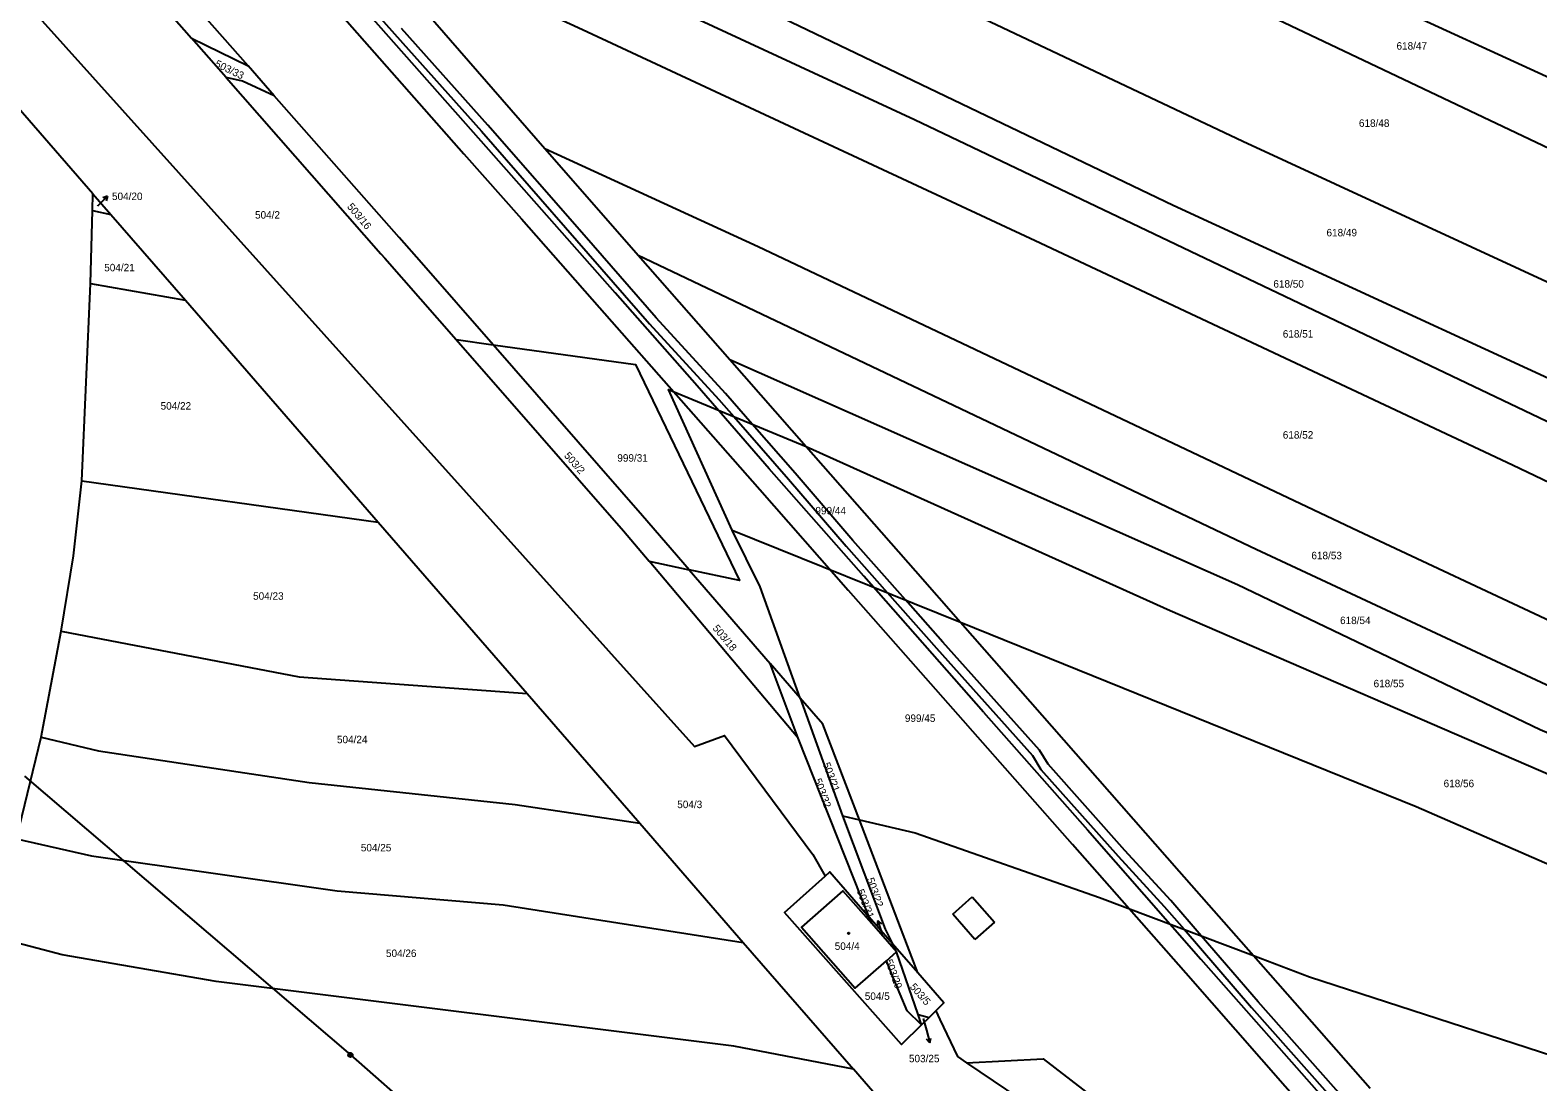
# Model space of a CAD drawing. Extents: x -757266 to -753360, y -1162585 to -1157740.
# Drawn here: x -755892 to -755548.3, y -1161804.6 to -1161564.9 of the extents above; entities that cross this region are included whole.
import ezdxf

# ---------------------------------------------------------------- set-up
doc = ezdxf.new("R2010")
doc.units = 0
for name, color, linetype in [('Hranice parcel', 7, 'Continuous'), ('Parcelní čísla', 7, 'Continuous'), ('Pop  PČ popisy', 7, 'Continuous'), ('Poz předměty', 7, 'Continuous'), ('Vnitřní kresba', 7, 'Continuous'), ('Věcná břemena k části', 7, 'Continuous'), ('Značky budov', 7, 'Continuous')]:
    doc.layers.add(name, color=color, linetype=linetype)

msp = doc.modelspace()

# ---------------------------------------------------------------- linework, layer by layer
at = {"layer": 'Hranice parcel'}
for p, q in [((-755847.28, -1161575.69), (-755855.21, -1161566.66)), ((-755855.21, -1161566.66), (-755842.32, -1161573.01)), ((-755877.68, -1161602.17), (-755901.54, -1161574.72)), ((-755836.33, -1161579.81), (-755842.32, -1161573.01)), ((-755877.79, -1161605.96), (-755877.68, -1161602.17)), ((-755877.68, -1161602.17), (-755873.56, -1161606.91)), ((-755878.21, -1161622.6), (-755877.79, -1161605.96)), ((-755877.79, -1161605.96), (-755873.56, -1161606.91)), ((-755873.56, -1161606.91), (-755856.6, -1161626.43)), ((-755753.39, -1161616.17), (-755732.49, -1161639.95)), ((-755880.2, -1161667.56), (-755878.21, -1161622.6)), ((-755878.21, -1161622.6), (-755856.6, -1161626.43)), ((-755856.6, -1161626.43), (-755812.66, -1161677)), ((-755794.91, -1161635.39), (-755786.48, -1161636.56)), ((-755732.49, -1161639.95), (-755715.13, -1161659.72)), ((-755880.2, -1161667.56), (-755812.66, -1161677)), ((-755812.66, -1161677), (-755778.7, -1161716.08)), ((-755731.95, -1161678.81), (-755679.92, -1161699.8)), ((-755716.94, -1161726.22), (-755750.9, -1161685.9)), ((-755750.9, -1161685.9), (-755741.74, -1161687.87)), ((-755741.74, -1161687.87), (-755723.29, -1161709.21)), ((-755889.47, -1161726.01), (-755884.94, -1161701.87)), ((-755716.94, -1161726.22), (-755723.29, -1161709.21)), ((-755716.45, -1161717.12), (-755723.29, -1161709.21)), ((-755778.7, -1161716.08), (-755753.05, -1161745.6)), ((-755716.45, -1161717.12), (-755706.82, -1161743.94)), ((-755895.05, -1161749.2), (-755889.47, -1161726.01)), ((-755700.77, -1161766.99), (-755716.94, -1161726.22)), ((-755706.82, -1161743.94), (-755702.99, -1161744.84)), ((-755753.05, -1161745.6), (-755729.44, -1161772.76)), ((-755700.18, -1161768.48), (-755700.77, -1161766.99)), ((-755695.42, -1161773.11), (-755700.77, -1161766.99)), ((-755694.5, -1161774.94), (-755700.18, -1161768.48)), ((-755729.44, -1161772.76), (-755704.31, -1161801.68)), ((-755696.81, -1161776.96), (-755694.5, -1161774.94)), ((-755694.5, -1161774.94), (-755695.42, -1161773.11)), ((-755689.64, -1161779.73), (-755695.42, -1161773.11)), ((-755689.6, -1161789.22), (-755694.5, -1161774.94)), ((-755613.16, -1161775.76), (-755586.56, -1161805.98)), ((-755688.8, -1161791.54), (-755689.6, -1161789.22)), ((-755689.6, -1161789.22), (-755687.09, -1161789.85)), ((-755687.09, -1161789.85), (-755685.57, -1161788.35)), ((-755688.8, -1161791.54), (-755687.09, -1161789.85)), ((-755674.25, -1161836.27), (-755704.31, -1161801.68)), ((-755678.58, -1161800.18), (-755654.29, -1161816.59))]:
    msp.add_line(p, q, dxfattribs=at)
for points in [[(-755892.54, -1161421.57), (-755867.71, -1161430.33), (-755791.73, -1161461.56), (-755748.48, -1161481.27), (-755612.94, -1161544.82), (-755515.47, -1161589.6), (-755468.37, -1161610.25), (-755307.39, -1161680.97), (-755272.91, -1161697.76)], [(-755891.29, -1161436.99), (-755870.09, -1161443.31), (-755786.81, -1161479.58), (-755750.28, -1161496.46), (-755622.77, -1161555.18), (-755538.15, -1161595.38), (-755482.94, -1161619.4), (-755320.06, -1161690.83), (-755285.14, -1161708.53)], [(-755880.56, -1161469.53), (-755866.2, -1161474.35), (-755794.39, -1161505.26), (-755743.31, -1161529.74), (-755615.6, -1161590.14), (-755500.37, -1161643.41), (-755448.3, -1161666.04), (-755370.47, -1161701.14), (-755333.96, -1161720.38), (-755313.13, -1161733.06)], [(-755853.46, -1161501.54), (-755831.78, -1161510.22), (-755748.22, -1161548.68), (-755631.49, -1161604.75), (-755509.83, -1161660.8), (-755424.9, -1161697.33), (-755394.64, -1161712), (-755349.72, -1161735.8), (-755331.06, -1161748.82)], [(-755841.68, -1161515.01), (-755690.42, -1161585.2), (-755543.08, -1161655.47), (-755436.92, -1161702.11), (-755374.35, -1161732.02), (-755353.78, -1161743.26), (-755338.85, -1161756)], [(-755842.32, -1161573.01), (-755859.87, -1161553.1), (-755868.89, -1161542.86), (-755884.45, -1161525.12)], [(-755937.42, -1161533.43), (-755908.94, -1161546.52), (-755890.58, -1161561.25), (-755740.56, -1161728.12), (-755733.69, -1161725.65), (-755713.56, -1161752.77), (-755710.79, -1161757.64)], [(-755879.08, -1161539.42), (-755873.01, -1161546.39), (-755870.91, -1161548.79), (-755855.21, -1161566.66)], [(-755819.86, -1161539.97), (-755766.1, -1161564.71), (-755662.93, -1161612.83), (-755554.11, -1161663.92), (-755480.53, -1161699.08), (-755432.93, -1161719.16), (-755401.15, -1161734.89), (-755367.57, -1161752.47), (-755348.98, -1161766.18)], [(-755819.86, -1161539.97), (-755809.5, -1161551.82), (-755774.64, -1161591.84)], [(-755836.33, -1161579.81), (-755843.59, -1161576.53), (-755847.28, -1161575.69)], [(-755847.28, -1161575.69), (-755812.06, -1161615.81), (-755811.14, -1161616.86), (-755794.91, -1161635.39)], [(-755786.48, -1161636.56), (-755802.79, -1161617.91), (-755807.87, -1161612.11), (-755836.33, -1161579.81)], [(-755774.64, -1161591.84), (-755726.03, -1161614.18), (-755589.33, -1161678.96), (-755454.18, -1161742.36), (-755402.44, -1161767.42), (-755369.85, -1161787.13)], [(-755774.64, -1161591.84), (-755759.73, -1161608.96), (-755753.39, -1161616.17)], [(-755753.39, -1161616.17), (-755612.54, -1161683.19), (-755473.53, -1161748.04), (-755438.73, -1161763.65), (-755402.06, -1161782.7), (-755384.87, -1161795.76)], [(-755794.91, -1161635.39), (-755756.73, -1161678.98), (-755750.9, -1161685.9)], [(-755741.74, -1161687.87), (-755752.39, -1161675.55), (-755786.48, -1161636.56)], [(-755786.48, -1161636.56), (-755753.97, -1161641.07), (-755730.34, -1161690.31), (-755741.74, -1161687.87)], [(-755732.49, -1161639.95), (-755616.84, -1161691.17), (-755547.82, -1161724.26), (-755503, -1161743.15), (-755442.16, -1161769.97), (-755400.95, -1161791.72), (-755390.8, -1161799.16)], [(-755731.95, -1161678.81), (-755746.49, -1161646.8), (-755715.13, -1161659.72)], [(-755715.13, -1161659.72), (-755632.13, -1161697.1), (-755512.71, -1161748.79), (-755451.69, -1161773.44), (-755408.92, -1161795.1), (-755397.69, -1161803.12)], [(-755715.13, -1161659.72), (-755690.22, -1161688.07), (-755679.92, -1161699.8)], [(-755884.94, -1161701.87), (-755882.07, -1161684.65), (-755880.2, -1161667.56)], [(-755716.45, -1161717.12), (-755725.56, -1161691.75), (-755731.95, -1161678.81)], [(-755679.92, -1161699.8), (-755576.09, -1161741.81), (-755531.35, -1161761.36), (-755446.03, -1161793.81), (-755424.05, -1161803.38), (-755408.45, -1161813.49)], [(-755679.92, -1161699.8), (-755630.12, -1161756.5), (-755613.16, -1161775.76)], [(-755884.94, -1161701.87), (-755830.68, -1161712.22), (-755778.7, -1161716.08)], [(-755702.99, -1161744.84), (-755711.34, -1161723.03), (-755716.45, -1161717.12)], [(-755889.47, -1161726.01), (-755876.4, -1161729.09), (-755828.38, -1161736.33), (-755781.41, -1161741.32), (-755753.05, -1161745.6)], [(-755706.82, -1161743.94), (-755697.12, -1161769.74), (-755695.42, -1161773.11)], [(-755702.99, -1161744.84), (-755690.28, -1161747.83), (-755648.24, -1161762.52), (-755613.16, -1161775.76)], [(-755689.64, -1161779.73), (-755693, -1161770.94), (-755702.99, -1161744.84)], [(-755704.31, -1161801.68), (-755731.6, -1161796.39), (-755849.56, -1161781.71), (-755884.67, -1161775.6), (-755902.08, -1161771.02), (-755895.05, -1161749.2)], [(-755895.05, -1161749.2), (-755878.03, -1161753.01), (-755821.97, -1161761.03), (-755784.18, -1161764.24), (-755729.44, -1161772.76)], [(-755688.8, -1161791.54), (-755693.35, -1161796.04), (-755720.04, -1161765.99), (-755710.79, -1161757.64)], [(-755710.79, -1161757.64), (-755709.75, -1161756.71), (-755700.77, -1161766.99)], [(-755700.18, -1161768.48), (-755706.76, -1161760.99), (-755716.21, -1161769.27), (-755703.95, -1161783.21), (-755696.81, -1161776.96)], [(-755688.8, -1161791.54), (-755692.06, -1161788.37), (-755695.31, -1161780.75), (-755696.81, -1161776.96)], [(-755613.16, -1161775.76), (-755600.36, -1161780.59), (-755527.35, -1161804.3), (-755473.37, -1161824.74), (-755443.67, -1161838.76)], [(-755685.57, -1161788.35), (-755683.72, -1161786.51), (-755689.64, -1161779.73)], [(-755685.57, -1161788.35), (-755684.64, -1161790.31), (-755680.65, -1161798.78), (-755678.58, -1161800.18)], [(-755678.58, -1161800.18), (-755661.1, -1161799.34), (-755627.88, -1161824.9), (-755622.76, -1161830.02), (-755594.02, -1161858.77), (-755590.93, -1161861.86), (-755546.55, -1161911.12), (-755543.23, -1161914.8), (-755538.69, -1161919.84), (-755486.83, -1161978.1), (-755450.61, -1162018.82), (-755447.56, -1162021.04), (-755444.3, -1162023.41), (-755440.24, -1162026.36), (-755403.56, -1162053.04), (-755357.6, -1162106.47), (-755332.83, -1162128.38)]]:
    msp.add_lwpolyline(points, dxfattribs=at)
at = {"layer": 'Pop  PČ popisy'}
for p, q in [((-755876.44, -1161604.86), (-755874.318, -1161602.738)), ((-755874.318, -1161602.738), (-755875.38, -1161603.092)), ((-755874.318, -1161602.738), (-755874.672, -1161603.8)), ((-755876.56, -1161604.98), (-755876.44, -1161604.86)), ((-755698.757, -1161767.753), (-755698.904, -1161768.862)), ((-755697.78, -1161770.59), (-755698.757, -1161767.753)), ((-755698.757, -1161767.753), (-755697.958, -1161768.536)), ((-755697.62, -1161771.06), (-755697.78, -1161770.59)), ((-755688.43, -1161790.13), (-755687.71, -1161792.78)), ((-755687.71, -1161792.78), (-755686.933, -1161795.679)), ((-755686.933, -1161795.679), (-755687.676, -1161794.841)), ((-755686.933, -1161795.679), (-755686.709, -1161794.582))]:
    msp.add_line(p, q, dxfattribs=at)
at = {"layer": 'Poz předměty'}
for p, q in [((-755789.21, -1161590.14), (-755847.85, -1161523.74)), ((-755851.39, -1161526.93), (-755793.1, -1161593.02)), ((-755793.1, -1161593.02), (-755780.02, -1161607.86)), ((-755758.65, -1161624.75), (-755789.21, -1161590.14)), ((-755780.02, -1161607.86), (-755762.24, -1161628.05)), ((-755739.95, -1161645.96), (-755758.65, -1161624.75)), ((-755762.24, -1161628.05), (-755743.6, -1161649.22)), ((-755723.58, -1161664.82), (-755739.95, -1161645.96)), ((-755743.6, -1161649.22), (-755725.68, -1161669.59)), ((-755702, -1161689.27), (-755723.58, -1161664.82)), ((-755725.68, -1161669.59), (-755705.56, -1161692.5)), ((-755674.71, -1161720.27), (-755702, -1161689.27)), ((-755705.56, -1161692.5), (-755678.25, -1161723.41)), ((-755674.71, -1161720.27), (-755650.98, -1161747.14)), ((-755654.41, -1161750.46), (-755678.25, -1161723.41)), ((-755893.28, -1161734.87), (-755818.98, -1161798.41)), ((-755650.98, -1161747.14), (-755625.13, -1161776.6)), ((-755628.59, -1161779.81), (-755654.41, -1161750.46)), ((-755625.13, -1161776.6), (-755595.92, -1161809.68)), ((-755599.51, -1161812.88), (-755628.59, -1161779.81)), ((-755818.98, -1161798.41), (-755749.35, -1161859.39))]:
    msp.add_line(p, q, dxfattribs=at)
for radius in [0.5, 0.4, 0.3, 0.2, 0.1]:
    msp.add_circle((-755818.9834, -1161798.4099), radius, dxfattribs=at)
at = {"layer": 'Vnitřní kresba'}
for p, q in [((-755681.7, -1161766.3), (-755677.25, -1161762.35)), ((-755677.25, -1161762.35), (-755672.16, -1161768.13)), ((-755676.66, -1161772.08), (-755681.7, -1161766.3)), ((-755672.16, -1161768.13), (-755676.66, -1161772.08))]:
    msp.add_line(p, q, dxfattribs=at)
at = {"layer": 'Věcná břemena k části'}
for points in [[(-755813.37, -1161560.78), (-755808.95, -1161565.68), (-755789.13, -1161587.86), (-755767.35, -1161612.8), (-755750.82, -1161631.79), (-755735, -1161649.05), (-755731.6, -1161652.93), (-755719.12, -1161667.19), (-755705.96, -1161682.5), (-755696.63, -1161693.06), (-755685.44, -1161705.72), (-755663.53, -1161730.14), (-755661.59, -1161733.37), (-755643.99, -1161753.13), (-755633.49, -1161764.57), (-755628.99, -1161769.78), (-755613.6, -1161787.63), (-755596.32, -1161807.13), (-755581.66, -1161823.46), (-755579.87, -1161825.44), (-755571.07, -1161835.25), (-755568.14, -1161838.9), (-755548.64, -1161860.96), (-755526.52, -1161886.05)], [(-755547.05, -1161859.74), (-755566.6, -1161837.62), (-755569.55, -1161833.95), (-755578.09, -1161824.42), (-755580.12, -1161822.18), (-755594.9, -1161805.71), (-755612.08, -1161786.34), (-755625.08, -1161771.26), (-755632.01, -1161763.22), (-755642.5, -1161751.79), (-755659.97, -1161732.17), (-755661.91, -1161728.95), (-755684, -1161704.33), (-755692.48, -1161694.73), (-755704.44, -1161681.2), (-755717.61, -1161665.87), (-755727.44, -1161654.65), (-755733.52, -1161647.71), (-755749.33, -1161630.45), (-755765.74, -1161611.61), (-755787.64, -1161586.53), (-755807.36, -1161564.46)]]:
    msp.add_lwpolyline(points, dxfattribs=at)
at = {"layer": 'Značky budov'}
msp.add_circle((-755705.4068, -1161770.7192), 0.175, dxfattribs=at)

# ---------------------------------------------------------------- texts
at = {"layer": 'Parcelní čísla'}
for s, p in [('618/47', (-755580.56, -1161569.31)), ('618/48', (-755589.13, -1161586.91)), ('504/20', (-755873.32, -1161603.59)), ('504/2', (-755840.72, -1161607.82)), ('618/49', (-755596.52, -1161611.86)), ('504/21', (-755875.09, -1161619.83)), ('618/50', (-755608.63, -1161623.55)), ('618/51', (-755606.48, -1161634.94)), ('504/22', (-755862.24, -1161651.35)), ('618/52', (-755606.48, -1161657.96)), ('999/31', (-755758.15, -1161663.21)), ('999/44', (-755713, -1161675.22)), ('618/53', (-755599.96, -1161685.45)), ('504/23', (-755841.16, -1161694.68)), ('618/54', (-755593.43, -1161700.23)), ('618/55', (-755585.79, -1161714.62)), ('999/45', (-755692.61, -1161722.52)), ('504/24', (-755822.05, -1161727.38)), ('618/56', (-755569.83, -1161737.4)), ('504/3', (-755744.49, -1161742.17)), ('504/25', (-755816.61, -1161752.03)), ('504/26', (-755810.88, -1161776.1)), ('504/4', (-755708.6, -1161774.47)), ('504/5', (-755701.75, -1161785.87)), ('503/25', (-755691.685, -1161800.088))]:
    msp.add_text(s, height=1.7, dxfattribs=at).set_placement(p)
for s, rotation, p in [('503/33', 334, (-755850.022, -1161573.093)), ('503/16', 310, (-755819.841, -1161605.156)), ('503/2', 311, (-755770.391, -1161661.917)), ('503/18', 310, (-755736.541, -1161701.236)), ('503/21', 290, (-755711.348, -1161732.1)), ('503/32', 290, (-755713.318, -1161735.75)), ('503/22', 289, (-755701.333, -1161758.346)), ('503/31', 290.999997, (-755703.613, -1161761.014)), ('503/29', 290, (-755697.118, -1161776.98)), ('503/5', 311, (-755691.591, -1161782.987))]:
    msp.add_text(s, height=1.7, rotation=rotation, dxfattribs=at).set_placement(p)

doc.saveas('drawing.dxf')
